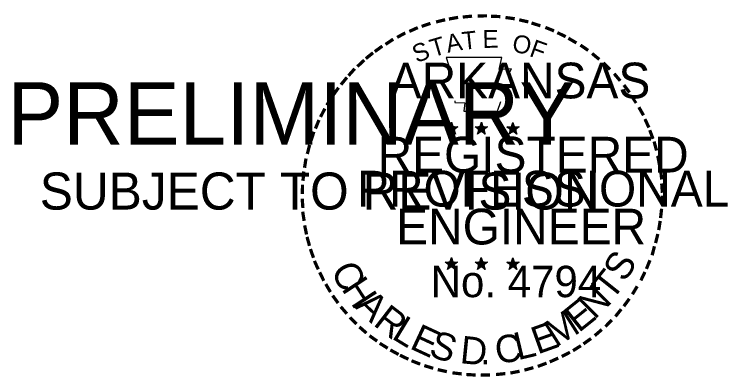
# Model space of a CAD drawing. Extents: x 3575 to 11445, y 9479 to 13278.
# Drawn here: x 5440 to 5639.4, y 12406.7 to 12508.2 of the extents above; entities that cross this region are included whole.
import ezdxf

# ---------------------------------------------------------------- set-up
doc = ezdxf.new("R2010")
doc.units = 0
doc.layers.add('STAMP_PE_FOSTER-SIGNATURE', color=7, linetype='Continuous')
doc.layers.add('STAMP_PE_SEAL-INFO', color=7, linetype='Continuous')

msp = doc.modelspace()

# ---------------------------------------------------------------- linework, layer by layer
at = {"layer": 'STAMP_PE_FOSTER-SIGNATURE'}
for p, q in [((5562.25, 12477.93), (5562.04, 12476.67)), ((5562.25, 12476.1), (5562.25, 12477.93)), ((5562.25, 12477.93), (5562.49, 12476.68)), ((5570.6, 12477.93), (5570.39, 12476.67)), ((5570.6, 12476.1), (5570.6, 12477.93)), ((5570.6, 12477.93), (5570.84, 12476.68)), ((5579.42, 12477.87), (5579.21, 12476.61)), ((5579.42, 12476.04), (5579.42, 12477.87)), ((5579.42, 12477.87), (5579.66, 12476.62)), ((5560.5, 12476.66), (5562.25, 12476.1)), ((5560.5, 12476.66), (5561.77, 12476.43)), ((5560.5, 12476.66), (5561.69, 12476.05)), ((5561.17, 12474.62), (5562.25, 12476.1)), ((5561.17, 12474.62), (5561.8, 12475.84)), ((5561.17, 12474.62), (5562.24, 12475.7)), ((5563.31, 12474.62), (5562.24, 12475.69)), ((5563.98, 12476.66), (5562.25, 12476.1)), ((5563.31, 12474.62), (5562.25, 12476.1)), ((5563.98, 12476.66), (5562.55, 12476.41)), ((5563.31, 12474.62), (5562.63, 12476.07)), ((5563.98, 12476.66), (5562.96, 12476.15)), ((5568.85, 12476.66), (5570.6, 12476.1)), ((5568.85, 12476.66), (5570.12, 12476.43)), ((5568.85, 12476.66), (5570.04, 12476.05)), ((5569.52, 12474.62), (5570.6, 12476.1)), ((5569.52, 12474.62), (5570.15, 12475.84)), ((5569.52, 12474.62), (5570.59, 12475.7)), ((5571.66, 12474.62), (5570.59, 12475.69)), ((5572.33, 12476.66), (5570.6, 12476.1)), ((5571.66, 12474.62), (5570.6, 12476.1)), ((5572.33, 12476.66), (5570.9, 12476.41)), ((5571.66, 12474.62), (5570.98, 12476.07)), ((5572.33, 12476.66), (5571.31, 12476.15)), ((5577.67, 12476.6), (5579.42, 12476.04)), ((5577.67, 12476.6), (5578.94, 12476.37)), ((5577.67, 12476.6), (5578.86, 12475.99)), ((5578.34, 12474.56), (5579.42, 12476.04)), ((5578.34, 12474.56), (5578.97, 12475.78)), ((5578.34, 12474.56), (5579.41, 12475.64)), ((5581.15, 12476.6), (5579.42, 12476.04)), ((5580.48, 12474.56), (5579.42, 12476.04)), ((5581.15, 12476.6), (5579.72, 12476.35)), ((5580.48, 12474.56), (5579.8, 12476.01)), ((5581.15, 12476.6), (5580.13, 12476.09)), ((5580.48, 12474.56), (5579.41, 12475.63)), ((5562.23, 12440.06), (5562.02, 12438.8)), ((5562.23, 12438.24), (5562.23, 12440.06)), ((5562.23, 12440.06), (5562.47, 12438.81)), ((5570.57, 12440.06), (5570.37, 12438.8)), ((5570.57, 12438.24), (5570.57, 12440.06)), ((5570.57, 12440.06), (5570.82, 12438.81)), ((5579.41, 12440.01), (5579.2, 12438.75)), ((5579.41, 12438.19), (5579.41, 12440.01)), ((5579.41, 12440.01), (5579.65, 12438.76)), ((5560.48, 12438.79), (5562.23, 12438.24)), ((5560.48, 12438.79), (5561.75, 12438.57)), ((5560.48, 12438.79), (5561.67, 12438.18)), ((5561.15, 12436.75), (5562.23, 12438.24)), ((5561.15, 12436.75), (5561.78, 12437.97)), ((5561.15, 12436.75), (5562.22, 12437.84)), ((5563.29, 12436.75), (5562.22, 12437.82)), ((5563.96, 12438.79), (5562.23, 12438.24)), ((5563.29, 12436.75), (5562.23, 12438.24)), ((5563.96, 12438.79), (5562.53, 12438.55)), ((5563.29, 12436.75), (5562.61, 12438.21)), ((5563.96, 12438.79), (5562.94, 12438.28)), ((5568.83, 12438.79), (5570.57, 12438.24)), ((5568.83, 12438.79), (5570.09, 12438.57)), ((5568.83, 12438.79), (5570.01, 12438.18)), ((5569.49, 12436.75), (5570.57, 12438.24)), ((5569.49, 12436.75), (5570.12, 12437.97)), ((5569.49, 12436.75), (5570.56, 12437.84)), ((5571.64, 12436.75), (5570.56, 12437.82)), ((5572.31, 12438.79), (5570.57, 12438.24)), ((5571.64, 12436.75), (5570.57, 12438.24)), ((5572.31, 12438.79), (5570.88, 12438.55)), ((5571.64, 12436.75), (5570.95, 12438.21)), ((5572.31, 12438.79), (5571.29, 12438.28)), ((5577.66, 12438.74), (5579.41, 12438.19)), ((5577.66, 12438.74), (5578.93, 12438.52)), ((5577.66, 12438.74), (5578.85, 12438.13)), ((5578.33, 12436.7), (5579.41, 12438.19)), ((5578.33, 12436.7), (5578.96, 12437.92)), ((5578.33, 12436.7), (5579.4, 12437.79)), ((5580.47, 12436.7), (5579.4, 12437.77)), ((5581.14, 12438.74), (5579.41, 12438.19)), ((5580.47, 12436.7), (5579.41, 12438.19)), ((5581.14, 12438.74), (5579.71, 12438.5)), ((5580.47, 12436.7), (5579.79, 12438.16)), ((5581.14, 12438.74), (5580.12, 12438.23))]:
    msp.add_line(p, q, dxfattribs=at)
for points in [[(5560.71, 12496.05), (5562.05, 12491.91)], [(5578.26, 12491.44), (5578.97, 12492.86), (5575.55, 12492.74), (5576.29, 12496.05), (5560.71, 12496.05)], [(5563.17, 12483.93), (5563.17, 12483.5), (5565.98, 12483.4), (5565.71, 12481.04), (5575.06, 12481.04), (5576.07, 12483.72)], [(5562.25, 12477.93), (5563.31, 12474.62), (5560.5, 12476.66), (5563.98, 12476.66), (5561.17, 12474.62), (5562.25, 12477.93)], [(5570.6, 12477.93), (5571.66, 12474.62), (5568.85, 12476.66), (5572.33, 12476.66), (5569.52, 12474.62), (5570.6, 12477.93)], [(5579.42, 12477.87), (5580.48, 12474.56), (5577.67, 12476.6), (5581.15, 12476.6), (5578.34, 12474.56), (5579.42, 12477.87)], [(5562.23, 12440.06), (5563.29, 12436.75), (5560.48, 12438.79), (5563.96, 12438.79), (5561.15, 12436.75), (5562.23, 12440.06)], [(5570.57, 12440.06), (5571.64, 12436.75), (5568.83, 12438.79), (5572.31, 12438.79), (5569.49, 12436.75), (5570.57, 12440.06)], [(5579.41, 12440.01), (5580.47, 12436.7), (5577.66, 12438.74), (5581.14, 12438.74), (5578.33, 12436.7), (5579.41, 12440.01)]]:
    msp.add_lwpolyline(points, dxfattribs=at)
for centre, radius in [((5562.24, 12476.1), 0.861), ((5562.24, 12476.1), 0.723), ((5562.24, 12476.1), 0.579), ((5562.24, 12476.1), 0.495), ((5562.24, 12476.1), 0.374), ((5562.24, 12476.1), 0.248), ((5562.24, 12476.1), 0.148), ((5570.59, 12476.1), 0.861), ((5570.59, 12476.1), 0.723), ((5570.59, 12476.1), 0.579), ((5570.59, 12476.1), 0.495), ((5570.59, 12476.1), 0.374), ((5570.59, 12476.1), 0.248), ((5570.59, 12476.1), 0.148), ((5579.41, 12476.04), 0.861), ((5579.41, 12476.04), 0.723), ((5579.41, 12476.04), 0.579), ((5579.41, 12476.04), 0.495), ((5579.41, 12476.04), 0.374), ((5579.41, 12476.04), 0.248), ((5579.41, 12476.04), 0.148), ((5562.22, 12438.24), 0.861), ((5562.22, 12438.24), 0.723), ((5562.22, 12438.24), 0.579), ((5562.22, 12438.24), 0.495), ((5562.22, 12438.24), 0.374), ((5562.22, 12438.24), 0.248), ((5562.22, 12438.24), 0.148), ((5570.57, 12438.24), 0.861), ((5570.57, 12438.24), 0.723), ((5570.57, 12438.24), 0.579), ((5570.57, 12438.24), 0.495), ((5570.57, 12438.24), 0.374), ((5570.57, 12438.24), 0.248), ((5570.57, 12438.24), 0.148), ((5579.4, 12438.19), 0.861), ((5579.4, 12438.19), 0.723), ((5579.4, 12438.19), 0.579), ((5579.4, 12438.19), 0.495), ((5579.4, 12438.19), 0.374), ((5579.4, 12438.19), 0.248), ((5579.4, 12438.19), 0.148)]:
    msp.add_circle(centre, radius, dxfattribs=at)

# ---------------------------------------------------------------- texts
for s, height, rotation, p in [('-', 8, 10.2193, (5561.59, 12503.7)), ('-', 8, 5.8968, (5565.23, 12504.25)), ('-', 8, 0.1862, (5569.09, 12504.61)), ('-', 8, 357.743, (5572.71, 12504.54)), ('-', 8, 352.1617, (5576.43, 12504.26)), ('-', 8, 19.1761, (5554.45, 12501.68)), ('-', 8, 13.6302, (5558.2, 12502.89)), ('-', 8, 347.2049, (5580.02, 12503.69)), ('-', 8, 342.3362, (5583.2, 12502.92)), ('-', 8, 24.3072, (5551.28, 12500.34)), ('T', 5, 6.0228, (5565.43, 12498.18)), ('E', 5, 0.8323, (5570.95, 12498.73)), ('-', 8, 337.8551, (5586.87, 12501.8)), ('-', 8, 34.0636, (5545.13, 12496.9)), ('-', 8, 28.7918, (5548.11, 12498.75)), ('T', 5, 16.4036, (5557.05, 12496.09)), ('A', 5, 11.2132, (5561.18, 12497.35)), ('O', 5, 350.4515, (5578.97, 12497.68)), ('-', 8, 334.1211, (5590.03, 12500.45)), ('-', 8, 329.6409, (5592.92, 12499.03)), ('-', 8, 36.2317, (5542.24, 12494.93)), ('S', 5, 21.594, (5552.48, 12494.44)), ('F', 5, 340.0707, (5583.74, 12496.54)), ('-', 8, 325.8627, (5596.14, 12497.23)), ('-', 8, 38.9507, (5539.86, 12493.04)), ('-', 8, 42.9622, (5537.69, 12490.95)), ('-', 8, 320.5297, (5599.19, 12495.1)), ('-', 8, 315.5786, (5602.18, 12492.66)), ('-', 8, 48.4231, (5535.45, 12488.56)), ('-', 8, 309.8797, (5605.03, 12489.91)), ('-', 8, 50.6142, (5533.44, 12486.13)), ('-', 8, 54.2325, (5531.37, 12483.3)), ('-', 8, 306.6522, (5607.65, 12486.9)), ('-', 8, 58.0706, (5529.75, 12480.66)), ('-', 7, 303.6753, (5610.08, 12484.06)), ('-', 8, 62.8713, (5528.18, 12477.59)), ('-', 8, 299.6684, (5611.68, 12481.02)), ('-', 8, 67.7743, (5526.89, 12474.54)), ('-', 8, 294.6628, (5613.3, 12477.96)), ('-', 8, 290.5728, (5614.58, 12475.08)), ('-', 8, 72.3945, (5525.79, 12471.39)), ('-', 8, 75.461, (5524.81, 12467.82)), ('-', 8, 285.1233, (5615.75, 12472.18)), ('-', 8, 81.2013, (5524.15, 12464.25)), ('-', 8, 280.5493, (5616.75, 12468.47)), ('-', 8, 85.1863, (5523.77, 12460.8)), ('-', 8, 276.5962, (5617.56, 12464.63)), ('-', 8, 89.0622, (5523.64, 12457.29)), ('-', 8, 274.3301, (5617.86, 12461.02)), ('-', 8, 94.1959, (5523.82, 12453.67)), ('-', 8, 269.9407, (5618.03, 12457.86)), ('-', 8, 263.5172, (5617.94, 12454.53)), ('-', 8, 98.9479, (5524.18, 12450.33)), ('-', 8, 260.9953, (5617.58, 12451.26)), ('-', 8, 101.7149, (5524.85, 12446.67)), ('-', 8, 105.4578, (5525.66, 12443.69)), ('-', 8, 255.7626, (5617.03, 12447.87)), ('-', 8, 109.0874, (5526.74, 12440.54)), ('-', 8, 255.7626, (5616.07, 12444.43)), ('S', 7.7, 57.878, (5610.69, 12432.9)), ('-', 8, 114.0643, (5528.01, 12437.56)), ('C', 7.7, 296.9133, (5528.37, 12436.52)), ('-', 8, 247.8887, (5615.01, 12440.9)), ('-', 8, 115.7289, (5529.53, 12434.47)), ('T', 7.7, 51.5114, (5607.04, 12427.69)), ('-', 8, 244.6197, (5613.7, 12437.76)), ('H', 7.7, 303.2799, (5531.33, 12431.31)), ('-', 8, 120.4471, (5531.32, 12431.54)), ('N', 7.7, 45.1449, (5602.24, 12422.48)), ('-', 8, 239.0712, (5611.73, 12434)), ('-', 8, 125.8934, (5533.33, 12428.73)), ('A', 7.7, 316.013, (5534.97, 12426.19)), ('E', 7.7, 38.7783, (5597.8, 12418.83)), ('-', 8, 233.8452, (5609.72, 12430.73)), ('-', 8, 130.7181, (5535.64, 12425.97)), ('R', 7.7, 322.3796, (5540.09, 12421.28)), ('-', 8, 231.2538, (5607.57, 12427.9)), ('M', 7.7, 32.4117, (5591.4, 12414.76)), ('-', 8, 134.2238, (5538.23, 12423.25)), ('L', 7.7, 328.7461, (5545.23, 12417.53)), ('E', 7.7, 19.6786, (5586.28, 12412.88)), ('-', 8, 225.7653, (5605.18, 12425.08)), ('-', 8, 138.9338, (5540.85, 12420.93)), ('E', 7.7, 335.1127, (5550.25, 12414.73)), ('-', 8, 221.0851, (5602.57, 12422.54)), ('-', 8, 144.6463, (5543.63, 12418.9)), ('S', 7.7, 341.4792, (5555.58, 12412.58)), ('D', 7.7, 354.2124, (5564.42, 12410.52)), ('C', 7.7, 6.9455, (5574.85, 12410.32)), ('L', 7.7, 13.3121, (5580.77, 12411.28)), ('-', 8, 148.0898, (5546.44, 12417.04)), ('-', 8, 215.7363, (5599.82, 12420.18)), ('-', 8, 151.5704, (5549.33, 12415.42)), ('-', 8, 207.3568, (5594.36, 12416.51)), ('-', 8, 212.2491, (5597.15, 12418.24)), ('-', 8, 154.6002, (5551.94, 12414.18)), ('-', 8, 204.2516, (5591.24, 12414.92)), ('-', 8, 158.5612, (5555.06, 12412.91)), ('-', 8, 162.7983, (5558.5, 12411.85)), ('.', 7.7, 0.5789, (5570.28, 12410.13)), ('-', 8, 200.7184, (5588.15, 12413.55)), ('-', 8, 167.5555, (5562.07, 12411.03)), ('-', 8, 173.1155, (5565.93, 12410.48)), ('-', 8, 185.8167, (5577.44, 12410.69)), ('-', 8, 191.2858, (5581.12, 12411.35)), ('-', 8, 195.4743, (5584.76, 12412.34)), ('-', 8, 176.5183, (5569.67, 12410.21)), ('-', 8, 181.5918, (5573.39, 12410.31))]:
    msp.add_text(s, height=height, rotation=rotation, dxfattribs=at).set_placement(p)
for s, height, p in [('ARKANSAS', 10, (5544.97, 12484.61)), ('REGISTERED', 10, (5541.58, 12463.86)), ('PROFESSIONAL', 10, (5535.84, 12454.34)), ('ENGINEER', 10, (5546.78, 12443.72)), ('No. 4794', 8.785, (5556.4, 12428.96))]:
    msp.add_text(s, height=height, dxfattribs=at).set_placement(p)
at = {"layer": 'STAMP_PE_SEAL-INFO'}
for s, height, p in [('PRELIMINARY', 17.5, (5438.13, 12471.63)), ('SUBJECT TO REVISION', 10.3756, (5447.17, 12453.48))]:
    msp.add_text(s, height=height, dxfattribs=at).set_placement(p)

doc.saveas('drawing.dxf')
